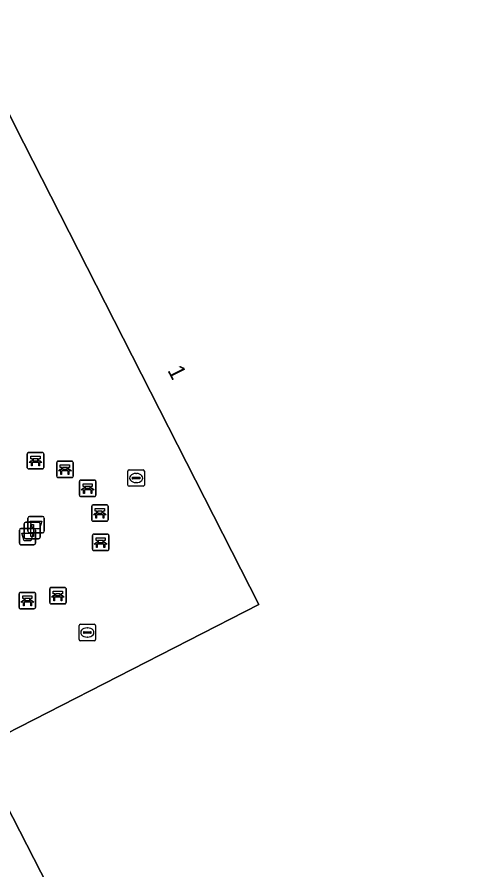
# Model space of a CAD drawing. Extents: x 158455 to 159797, y 387218 to 388672.
# Drawn here: x 159149.7 to 159177.5, y 387581.8 to 387633.9 of the extents above; entities that cross this region are included whole.
import ezdxf

# ---------------------------------------------------------------- set-up
doc = ezdxf.new("R2010")
doc.units = 0
for name, color, linetype in [('IMGEO_Afvalbak', 7, 'Continuous'), ('IMGEO_Bank', 7, 'Continuous'), ('IMGEO_Kolk', 7, 'Continuous'), ('IMGEO_Lichtmast', 7, 'Continuous'), ('IMGEO_Pand', 7, 'Continuous'), ('IMGEO_Pand_nummerreeks', 7, 'Continuous'), ('IMGEO_Voetpad_open', 7, 'Continuous')]:
    doc.layers.add(name, color=color, linetype=linetype)

msp = doc.modelspace()

# ---------------------------------------------------------------- linework, layer by layer
at = {"layer": 'IMGEO_Afvalbak'}
for p, q in [((159150.321, 387602.529), (159150.321, 387603.329)), ((159150.321, 387603.329), (159150.321, 387602.529)), ((159150.421, 387603.429), (159151.211, 387603.429)), ((159151.211, 387603.429), (159150.421, 387603.429)), ((159151.311, 387603.329), (159151.311, 387602.529)), ((159151.311, 387602.529), (159151.311, 387603.329)), ((159149.895, 387602.703), (159150.685, 387602.703)), ((159150.685, 387602.703), (159149.895, 387602.703)), ((159149.795, 387601.803), (159149.795, 387602.603)), ((159149.795, 387602.603), (159149.795, 387601.803)), ((159151.211, 387602.429), (159150.421, 387602.429)), ((159150.421, 387602.429), (159151.211, 387602.429)), ((159150.785, 387602.603), (159150.785, 387601.803)), ((159150.785, 387601.803), (159150.785, 387602.603)), ((159150.685, 387601.703), (159149.895, 387601.703)), ((159149.895, 387601.703), (159150.685, 387601.703))]:
    msp.add_line(p, q, dxfattribs=at)
for points in [[(159150.464, 387603.143), (159151.168, 387603.143), (159151.019, 387602.673), (159150.613, 387602.673), (159150.464, 387603.143)], [(159149.938, 387602.417), (159150.642, 387602.417), (159150.493, 387601.947), (159150.087, 387601.947), (159149.938, 387602.417)]]:
    msp.add_lwpolyline(points, dxfattribs=at)
for centre, start, end in [((159150.421, 387603.329), 90, 180), ((159150.421, 387603.329), 90, 180), ((159151.211, 387603.329), 0, 90), ((159151.211, 387603.329), 360, 90), ((159149.895, 387602.603), 90, 180), ((159149.895, 387602.603), 90, 180), ((159150.685, 387602.603), 0, 90), ((159150.685, 387602.603), 360, 90), ((159150.421, 387602.529), 180, 270), ((159150.421, 387602.529), 180, 270), ((159151.211, 387602.529), 270, 0), ((159151.211, 387602.529), 270, 0), ((159149.895, 387601.803), 180, 270), ((159149.895, 387601.803), 180, 270), ((159150.685, 387601.803), 270, 0), ((159150.685, 387601.803), 270, 0)]:
    msp.add_arc(centre, 0.1, start, end, dxfattribs=at)
at = {"layer": 'IMGEO_Bank'}
for p, q in [((159150.281, 387606.412), (159150.281, 387607.253)), ((159150.281, 387607.253), (159150.281, 387606.412)), ((159150.356, 387607.337), (159151.197, 387607.337)), ((159151.197, 387607.337), (159150.356, 387607.337)), ((159150.59, 387606.843), (159150.59, 387606.949)), ((159150.634, 387606.949), (159150.634, 387606.843)), ((159150.922, 387606.955), (159150.64, 387606.955)), ((159150.928, 387606.843), (159150.928, 387606.949)), ((159150.972, 387606.949), (159150.972, 387606.843)), ((159151.281, 387607.262), (159151.281, 387606.421)), ((159151.281, 387606.421), (159151.281, 387607.262)), ((159150.978, 387606.735), (159150.585, 387606.735)), ((159150.64, 387606.837), (159150.922, 387606.837)), ((159152.077, 387605.886), (159152.077, 387606.727)), ((159152.077, 387606.727), (159152.077, 387605.886)), ((159152.152, 387606.811), (159152.993, 387606.811)), ((159152.993, 387606.811), (159152.152, 387606.811)), ((159152.386, 387606.317), (159152.386, 387606.423)), ((159152.43, 387606.423), (159152.43, 387606.317)), ((159152.718, 387606.429), (159152.436, 387606.429)), ((159152.724, 387606.317), (159152.724, 387606.423)), ((159152.768, 387606.423), (159152.768, 387606.317)), ((159153.077, 387606.736), (159153.077, 387605.895)), ((159153.077, 387605.895), (159153.077, 387606.736)), ((159151.206, 387606.337), (159150.365, 387606.337)), ((159150.365, 387606.337), (159151.206, 387606.337)), ((159152.774, 387606.209), (159152.381, 387606.209)), ((159152.436, 387606.311), (159152.718, 387606.311)), ((159153.002, 387605.811), (159152.161, 387605.811)), ((159152.161, 387605.811), (159153.002, 387605.811)), ((159153.467, 387604.726), (159153.467, 387605.567)), ((159153.467, 387605.567), (159153.467, 387604.726)), ((159153.542, 387605.651), (159154.383, 387605.651)), ((159154.383, 387605.651), (159153.542, 387605.651)), ((159154.467, 387605.576), (159154.467, 387604.735)), ((159154.467, 387604.735), (159154.467, 387605.576)), ((159154.164, 387605.049), (159153.771, 387605.049)), ((159153.776, 387605.157), (159153.776, 387605.263)), ((159153.82, 387605.263), (159153.82, 387605.157)), ((159154.108, 387605.269), (159153.826, 387605.269)), ((159153.826, 387605.151), (159154.108, 387605.151)), ((159154.114, 387605.157), (159154.114, 387605.263)), ((159154.158, 387605.263), (159154.158, 387605.157)), ((159154.392, 387604.651), (159153.551, 387604.651)), ((159153.551, 387604.651), (159154.392, 387604.651)), ((159154.21, 387603.213), (159154.21, 387604.054)), ((159154.21, 387604.054), (159154.21, 387603.213)), ((159154.285, 387604.138), (159155.126, 387604.138)), ((159155.126, 387604.138), (159154.285, 387604.138)), ((159154.519, 387603.644), (159154.519, 387603.75)), ((159154.563, 387603.75), (159154.563, 387603.644)), ((159154.851, 387603.756), (159154.569, 387603.756)), ((159154.857, 387603.644), (159154.857, 387603.75)), ((159154.901, 387603.75), (159154.901, 387603.644)), ((159155.21, 387604.063), (159155.21, 387603.222)), ((159155.21, 387603.222), (159155.21, 387604.063)), ((159154.907, 387603.536), (159154.514, 387603.536)), ((159154.569, 387603.638), (159154.851, 387603.638)), ((159155.135, 387603.138), (159154.294, 387603.138)), ((159154.294, 387603.138), (159155.135, 387603.138)), ((159154.257, 387601.426), (159154.257, 387602.267)), ((159154.257, 387602.267), (159154.257, 387601.426)), ((159154.332, 387602.351), (159155.173, 387602.351)), ((159155.173, 387602.351), (159154.332, 387602.351)), ((159155.257, 387602.276), (159155.257, 387601.435)), ((159155.257, 387601.435), (159155.257, 387602.276)), ((159154.954, 387601.749), (159154.561, 387601.749)), ((159154.566, 387601.857), (159154.566, 387601.963)), ((159154.61, 387601.963), (159154.61, 387601.857)), ((159154.898, 387601.969), (159154.616, 387601.969)), ((159154.616, 387601.851), (159154.898, 387601.851)), ((159154.904, 387601.857), (159154.904, 387601.963)), ((159154.948, 387601.963), (159154.948, 387601.857)), ((159155.182, 387601.351), (159154.341, 387601.351)), ((159154.341, 387601.351), (159155.182, 387601.351)), ((159151.722, 387599.099), (159152.563, 387599.099)), ((159152.563, 387599.099), (159151.722, 387599.099)), ((159149.785, 387597.872), (159149.785, 387598.713)), ((159149.785, 387598.713), (159149.785, 387597.872)), ((159149.86, 387598.797), (159150.701, 387598.797)), ((159150.701, 387598.797), (159149.86, 387598.797)), ((159150.785, 387598.722), (159150.785, 387597.881)), ((159150.785, 387597.881), (159150.785, 387598.722)), ((159151.647, 387598.174), (159151.647, 387599.015)), ((159151.647, 387599.015), (159151.647, 387598.174)), ((159151.956, 387598.605), (159151.956, 387598.711)), ((159152, 387598.711), (159152, 387598.605)), ((159152.288, 387598.717), (159152.006, 387598.717)), ((159152.006, 387598.599), (159152.288, 387598.599)), ((159152.294, 387598.605), (159152.294, 387598.711)), ((159152.338, 387598.711), (159152.338, 387598.605)), ((159152.647, 387599.024), (159152.647, 387598.183)), ((159152.647, 387598.183), (159152.647, 387599.024)), ((159150.482, 387598.195), (159150.089, 387598.195)), ((159150.094, 387598.303), (159150.094, 387598.409)), ((159150.138, 387598.409), (159150.138, 387598.303)), ((159150.426, 387598.415), (159150.144, 387598.415)), ((159150.144, 387598.297), (159150.426, 387598.297)), ((159150.432, 387598.303), (159150.432, 387598.409)), ((159150.476, 387598.409), (159150.476, 387598.303)), ((159152.572, 387598.099), (159151.731, 387598.099)), ((159151.731, 387598.099), (159152.572, 387598.099)), ((159152.344, 387598.497), (159151.951, 387598.497)), ((159150.71, 387597.797), (159149.869, 387597.797)), ((159149.869, 387597.797), (159150.71, 387597.797))]:
    msp.add_line(p, q, dxfattribs=at)
for points in [[(159150.584, 387606.955), (159150.498, 387606.955), (159150.498, 387607.116), (159151.061, 387607.116), (159151.061, 387606.955), (159150.978, 387606.955)], [(159150.528, 387606.735), (159150.386, 387606.735), (159150.498, 387606.837), (159150.584, 387606.837)], [(159150.578, 387606.728), (159150.578, 387606.521), (159150.535, 387606.521), (159150.535, 387606.728)], [(159150.978, 387606.837), (159151.061, 387606.837), (159151.173, 387606.735), (159151.034, 387606.735)], [(159151.028, 387606.728), (159151.028, 387606.521), (159150.984, 387606.521), (159150.984, 387606.728)], [(159152.38, 387606.429), (159152.294, 387606.429), (159152.294, 387606.59), (159152.857, 387606.59), (159152.857, 387606.429), (159152.774, 387606.429)], [(159152.324, 387606.209), (159152.182, 387606.209), (159152.294, 387606.311), (159152.38, 387606.311)], [(159152.374, 387606.202), (159152.374, 387605.995), (159152.331, 387605.995), (159152.331, 387606.202)], [(159152.774, 387606.311), (159152.857, 387606.311), (159152.969, 387606.209), (159152.83, 387606.209)], [(159152.824, 387606.202), (159152.824, 387605.995), (159152.78, 387605.995), (159152.78, 387606.202)], [(159153.77, 387605.269), (159153.684, 387605.269), (159153.684, 387605.43), (159154.247, 387605.43), (159154.247, 387605.269), (159154.164, 387605.269)], [(159153.714, 387605.049), (159153.572, 387605.049), (159153.684, 387605.151), (159153.77, 387605.151)], [(159153.764, 387605.042), (159153.764, 387604.835), (159153.721, 387604.835), (159153.721, 387605.042)], [(159154.164, 387605.151), (159154.247, 387605.151), (159154.359, 387605.049), (159154.22, 387605.049)], [(159154.214, 387605.042), (159154.214, 387604.835), (159154.17, 387604.835), (159154.17, 387605.042)], [(159154.513, 387603.756), (159154.427, 387603.756), (159154.427, 387603.917), (159154.99, 387603.917), (159154.99, 387603.756), (159154.907, 387603.756)], [(159154.457, 387603.536), (159154.315, 387603.536), (159154.427, 387603.638), (159154.513, 387603.638)], [(159154.507, 387603.529), (159154.507, 387603.322), (159154.464, 387603.322), (159154.464, 387603.529)], [(159154.907, 387603.638), (159154.99, 387603.638), (159155.102, 387603.536), (159154.963, 387603.536)], [(159154.957, 387603.529), (159154.957, 387603.322), (159154.913, 387603.322), (159154.913, 387603.529)], [(159154.504, 387601.749), (159154.362, 387601.749), (159154.474, 387601.851), (159154.56, 387601.851)], [(159154.56, 387601.969), (159154.474, 387601.969), (159154.474, 387602.13), (159155.037, 387602.13), (159155.037, 387601.969), (159154.954, 387601.969)], [(159154.554, 387601.742), (159154.554, 387601.535), (159154.511, 387601.535), (159154.511, 387601.742)], [(159154.954, 387601.851), (159155.037, 387601.851), (159155.149, 387601.749), (159155.01, 387601.749)], [(159155.004, 387601.742), (159155.004, 387601.535), (159154.96, 387601.535), (159154.96, 387601.742)], [(159150.088, 387598.415), (159150.002, 387598.415), (159150.002, 387598.576), (159150.565, 387598.576), (159150.565, 387598.415), (159150.482, 387598.415)], [(159151.894, 387598.497), (159151.752, 387598.497), (159151.864, 387598.599), (159151.95, 387598.599)], [(159151.95, 387598.717), (159151.864, 387598.717), (159151.864, 387598.878), (159152.427, 387598.878), (159152.427, 387598.717), (159152.344, 387598.717)], [(159152.344, 387598.599), (159152.427, 387598.599), (159152.539, 387598.497), (159152.4, 387598.497)], [(159150.032, 387598.195), (159149.89, 387598.195), (159150.002, 387598.297), (159150.088, 387598.297)], [(159150.082, 387598.188), (159150.082, 387597.981), (159150.039, 387597.981), (159150.039, 387598.188)], [(159150.482, 387598.297), (159150.565, 387598.297), (159150.677, 387598.195), (159150.538, 387598.195)], [(159150.532, 387598.188), (159150.532, 387597.981), (159150.488, 387597.981), (159150.488, 387598.188)], [(159151.944, 387598.49), (159151.944, 387598.283), (159151.901, 387598.283), (159151.901, 387598.49)], [(159152.394, 387598.49), (159152.394, 387598.283), (159152.35, 387598.283), (159152.35, 387598.49)]]:
    msp.add_lwpolyline(points, dxfattribs=at)
for centre, radius, start, end in [((159150.359, 387607.259), 0.0779, 92.4484, 184.2845), ((159150.359, 387607.259), 0.0779, 92.4484, 184.2845), ((159150.583, 387606.948), 0.00671, 2.8957, 87.1043), ((159150.64, 387606.948), 0.00671, 92.8957, 177.1043), ((159150.922, 387606.948), 0.00671, 2.8957, 87.1043), ((159150.979, 387606.948), 0.00671, 92.8957, 177.1043), ((159151.203, 387607.259), 0.0779, 2.4484, 94.2845), ((159151.203, 387607.259), 0.0779, 2.4484, 94.2845), ((159150.359, 387606.415), 0.0779, 182.4484, 274.2845), ((159150.359, 387606.415), 0.0779, 182.4484, 274.2845), ((159150.528, 387606.728), 0.00671, 2.8957, 87.1043), ((159150.585, 387606.728), 0.00671, 92.8957, 177.1043), ((159150.583, 387606.844), 0.00671, 272.8957, 357.1043), ((159150.64, 387606.844), 0.00671, 182.8957, 267.1043), ((159150.922, 387606.844), 0.00671, 272.8957, 357.1043), ((159150.979, 387606.844), 0.00671, 182.8957, 267.1043), ((159150.977, 387606.728), 0.00671, 2.8957, 87.1043), ((159151.034, 387606.728), 0.00671, 92.8957, 177.1043), ((159151.203, 387606.415), 0.0779, 272.4484, 4.2845), ((159151.203, 387606.415), 0.0779, 272.4484, 4.2845), ((159152.155, 387606.733), 0.0779, 92.4484, 184.2845), ((159152.155, 387606.733), 0.0779, 92.4484, 184.2845), ((159152.379, 387606.422), 0.00671, 2.8957, 87.1043), ((159152.436, 387606.422), 0.00671, 92.8957, 177.1043), ((159152.718, 387606.422), 0.00671, 2.8957, 87.1043), ((159152.775, 387606.422), 0.00671, 92.8957, 177.1043), ((159152.999, 387606.733), 0.0779, 2.4484, 94.2845), ((159152.999, 387606.733), 0.0779, 2.4484, 94.2845), ((159152.155, 387605.889), 0.0779, 182.4484, 274.2845), ((159152.155, 387605.889), 0.0779, 182.4484, 274.2845), ((159152.324, 387606.202), 0.00671, 2.8957, 87.1043), ((159152.381, 387606.202), 0.00671, 92.8957, 177.1043), ((159152.379, 387606.318), 0.00671, 272.8957, 357.1043), ((159152.436, 387606.318), 0.00671, 182.8957, 267.1043), ((159152.718, 387606.318), 0.00671, 272.8957, 357.1043), ((159152.775, 387606.318), 0.00671, 182.8957, 267.1043), ((159152.773, 387606.202), 0.00671, 2.8957, 87.1043), ((159152.83, 387606.202), 0.00671, 92.8957, 177.1043), ((159152.999, 387605.889), 0.0779, 272.4484, 4.2845), ((159152.999, 387605.889), 0.0779, 272.4484, 4.2845), ((159153.545, 387605.573), 0.0779, 92.4484, 184.2845), ((159153.545, 387605.573), 0.0779, 92.4484, 184.2845), ((159154.389, 387605.573), 0.0779, 2.4484, 94.2845), ((159154.389, 387605.573), 0.0779, 2.4484, 94.2845), ((159153.714, 387605.042), 0.00671, 2.8957, 87.1043), ((159153.771, 387605.042), 0.00671, 92.8957, 177.1043), ((159153.769, 387605.262), 0.00671, 2.8957, 87.1043), ((159153.769, 387605.158), 0.00671, 272.8957, 357.1043), ((159153.826, 387605.262), 0.00671, 92.8957, 177.1043), ((159153.826, 387605.158), 0.00671, 182.8957, 267.1043), ((159154.108, 387605.262), 0.00671, 2.8957, 87.1043), ((159154.108, 387605.158), 0.00671, 272.8957, 357.1043), ((159154.165, 387605.262), 0.00671, 92.8957, 177.1043), ((159154.165, 387605.158), 0.00671, 182.8957, 267.1043), ((159154.163, 387605.042), 0.00671, 2.8957, 87.1043), ((159154.22, 387605.042), 0.00671, 92.8957, 177.1043), ((159153.545, 387604.729), 0.0779, 182.4484, 274.2845), ((159153.545, 387604.729), 0.0779, 182.4484, 274.2845), ((159154.389, 387604.729), 0.0779, 272.4484, 4.2845), ((159154.389, 387604.729), 0.0779, 272.4484, 4.2845), ((159154.288, 387604.06), 0.0779, 92.4484, 184.2845), ((159154.288, 387604.06), 0.0779, 92.4484, 184.2845), ((159154.512, 387603.749), 0.00671, 2.8957, 87.1043), ((159154.569, 387603.749), 0.00671, 92.8957, 177.1043), ((159154.851, 387603.749), 0.00671, 2.8957, 87.1043), ((159154.908, 387603.749), 0.00671, 92.8957, 177.1043), ((159155.132, 387604.06), 0.0779, 2.4484, 94.2845), ((159155.132, 387604.06), 0.0779, 2.4484, 94.2845), ((159154.457, 387603.529), 0.00671, 2.8957, 87.1043), ((159154.514, 387603.529), 0.00671, 92.8957, 177.1043), ((159154.512, 387603.645), 0.00671, 272.8957, 357.1043), ((159154.569, 387603.645), 0.00671, 182.8957, 267.1043), ((159154.851, 387603.645), 0.00671, 272.8957, 357.1043), ((159154.908, 387603.645), 0.00671, 182.8957, 267.1043), ((159154.906, 387603.529), 0.00671, 2.8957, 87.1043), ((159154.963, 387603.529), 0.00671, 92.8957, 177.1043), ((159155.132, 387603.216), 0.0779, 272.4484, 4.2845), ((159155.132, 387603.216), 0.0779, 272.4484, 4.2845), ((159154.288, 387603.216), 0.0779, 182.4484, 274.2845), ((159154.288, 387603.216), 0.0779, 182.4484, 274.2845), ((159154.335, 387602.273), 0.0779, 92.4484, 184.2845), ((159154.335, 387602.273), 0.0779, 92.4484, 184.2845), ((159155.179, 387602.273), 0.0779, 2.4484, 94.2845), ((159155.179, 387602.273), 0.0779, 2.4484, 94.2845), ((159154.504, 387601.742), 0.00671, 2.8957, 87.1043), ((159154.561, 387601.742), 0.00671, 92.8957, 177.1043), ((159154.559, 387601.962), 0.00671, 2.8957, 87.1043), ((159154.559, 387601.858), 0.00671, 272.8957, 357.1043), ((159154.616, 387601.962), 0.00671, 92.8957, 177.1043), ((159154.616, 387601.858), 0.00671, 182.8957, 267.1043), ((159154.898, 387601.962), 0.00671, 2.8957, 87.1043), ((159154.898, 387601.858), 0.00671, 272.8957, 357.1043), ((159154.955, 387601.962), 0.00671, 92.8957, 177.1043), ((159154.955, 387601.858), 0.00671, 182.8957, 267.1043), ((159154.953, 387601.742), 0.00671, 2.8957, 87.1043), ((159155.01, 387601.742), 0.00671, 92.8957, 177.1043), ((159154.335, 387601.429), 0.0779, 182.4484, 274.2845), ((159154.335, 387601.429), 0.0779, 182.4484, 274.2845), ((159155.179, 387601.429), 0.0779, 272.4484, 4.2845), ((159155.179, 387601.429), 0.0779, 272.4484, 4.2845), ((159151.725, 387599.021), 0.0779, 92.4484, 184.2845), ((159151.725, 387599.021), 0.0779, 92.4484, 184.2845), ((159152.569, 387599.021), 0.0779, 2.4484, 94.2845), ((159152.569, 387599.021), 0.0779, 2.4484, 94.2845), ((159149.863, 387598.719), 0.0779, 92.4484, 184.2845), ((159149.863, 387598.719), 0.0779, 92.4484, 184.2845), ((159150.707, 387598.719), 0.0779, 2.4484, 94.2845), ((159150.707, 387598.719), 0.0779, 2.4484, 94.2845), ((159151.949, 387598.71), 0.00671, 2.8957, 87.1043), ((159151.949, 387598.606), 0.00671, 272.8957, 357.1043), ((159152.006, 387598.71), 0.00671, 92.8957, 177.1043), ((159152.006, 387598.606), 0.00671, 182.8957, 267.1043), ((159152.288, 387598.71), 0.00671, 2.8957, 87.1043), ((159152.288, 387598.606), 0.00671, 272.8957, 357.1043), ((159152.345, 387598.71), 0.00671, 92.8957, 177.1043), ((159152.345, 387598.606), 0.00671, 182.8957, 267.1043), ((159150.032, 387598.188), 0.00671, 2.8957, 87.1043), ((159150.089, 387598.188), 0.00671, 92.8957, 177.1043), ((159150.087, 387598.408), 0.00671, 2.8957, 87.1043), ((159150.087, 387598.304), 0.00671, 272.8957, 357.1043), ((159150.144, 387598.408), 0.00671, 92.8957, 177.1043), ((159150.144, 387598.304), 0.00671, 182.8957, 267.1043), ((159150.426, 387598.408), 0.00671, 2.8957, 87.1043), ((159150.426, 387598.304), 0.00671, 272.8957, 357.1043), ((159150.483, 387598.408), 0.00671, 92.8957, 177.1043), ((159150.483, 387598.304), 0.00671, 182.8957, 267.1043), ((159150.481, 387598.188), 0.00671, 2.8957, 87.1043), ((159150.538, 387598.188), 0.00671, 92.8957, 177.1043), ((159151.725, 387598.177), 0.0779, 182.4484, 274.2845), ((159151.725, 387598.177), 0.0779, 182.4484, 274.2845), ((159151.894, 387598.49), 0.00671, 2.8957, 87.1043), ((159151.951, 387598.49), 0.00671, 92.8957, 177.1043), ((159152.343, 387598.49), 0.00671, 2.8957, 87.1043), ((159152.4, 387598.49), 0.00671, 92.8957, 177.1043), ((159152.569, 387598.177), 0.0779, 272.4484, 4.2845), ((159152.569, 387598.177), 0.0779, 272.4484, 4.2845), ((159149.863, 387597.875), 0.0779, 182.4484, 274.2845), ((159149.863, 387597.875), 0.0779, 182.4484, 274.2845), ((159150.707, 387597.875), 0.0779, 272.4484, 4.2845), ((159150.707, 387597.875), 0.0779, 272.4484, 4.2845)]:
    msp.add_arc(centre, radius, start, end, dxfattribs=at)
at = {"layer": 'IMGEO_Kolk'}
for p, q in [((159156.423, 387605.353), (159156.423, 387606.205)), ((159156.498, 387606.279), (159157.35, 387606.279)), ((159156.725, 387605.822), (159157.123, 387605.822)), ((159156.911, 387606.059), (159156.936, 387606.059)), ((159157.424, 387606.205), (159157.424, 387605.353)), ((159156.682, 387605.773), (159156.682, 387605.785)), ((159157.12, 387605.736), (159156.722, 387605.736)), ((159156.934, 387605.499), (159156.909, 387605.499)), ((159157.166, 387605.785), (159157.166, 387605.773)), ((159157.35, 387605.279), (159156.498, 387605.279)), ((159153.443, 387595.919), (159153.443, 387596.771)), ((159153.518, 387596.845), (159154.37, 387596.845)), ((159153.931, 387596.625), (159153.956, 387596.625)), ((159154.444, 387596.771), (159154.444, 387595.919)), ((159153.702, 387596.339), (159153.702, 387596.351)), ((159154.14, 387596.302), (159153.742, 387596.302)), ((159153.745, 387596.388), (159154.143, 387596.388)), ((159153.954, 387596.065), (159153.929, 387596.065)), ((159154.186, 387596.351), (159154.186, 387596.339)), ((159154.37, 387595.845), (159153.518, 387595.845))]:
    msp.add_line(p, q, dxfattribs=at)
for points in [[(159156.423, 387605.353), (159156.423, 387606.205)], [(159156.498, 387606.279), (159157.35, 387606.279)], [(159157.424, 387606.205), (159157.424, 387605.353)], [(159157.35, 387605.279), (159156.498, 387605.279)], [(159153.443, 387595.919), (159153.443, 387596.771)], [(159153.518, 387596.845), (159154.37, 387596.845)], [(159154.444, 387596.771), (159154.444, 387595.919)], [(159154.37, 387595.845), (159153.518, 387595.845)]]:
    msp.add_lwpolyline(points, dxfattribs=at)
for centre, radius, start, end in [((159156.5, 387606.203), 0.0765, 91.552, 178.448), ((159156.5, 387606.203), 0.0765, 91.552, 178.448), ((159156.722, 387605.782), 0.0403, 85.8775, 175.7526), ((159157.127, 387605.784), 0.0386, 1.7309, 96.639), ((159157.348, 387606.203), 0.0765, 1.552, 88.448), ((159157.348, 387606.203), 0.0765, 1.552, 88.448), ((159156.5, 387605.355), 0.0765, 181.552, 268.448), ((159156.5, 387605.355), 0.0765, 181.552, 268.448), ((159156.719, 387605.772), 0.0366, 178.938, 274.7102), ((159157.123, 387605.779), 0.043, 264.8664, 352.4533), ((159157.348, 387605.355), 0.0765, 271.552, 358.448), ((159157.348, 387605.355), 0.0765, 271.552, 358.448), ((159153.52, 387596.769), 0.0765, 91.552, 178.448), ((159153.52, 387596.769), 0.0765, 91.552, 178.448), ((159154.368, 387596.769), 0.0765, 1.552, 88.448), ((159154.368, 387596.769), 0.0765, 1.552, 88.448), ((159153.742, 387596.348), 0.0403, 85.8775, 175.7526), ((159153.739, 387596.338), 0.0366, 178.938, 274.7102), ((159154.143, 387596.345), 0.043, 264.8664, 352.4533), ((159154.147, 387596.35), 0.0386, 1.7309, 96.639), ((159153.52, 387595.921), 0.0765, 181.552, 268.448), ((159153.52, 387595.921), 0.0765, 181.552, 268.448), ((159154.368, 387595.921), 0.0765, 271.552, 358.448), ((159154.368, 387595.921), 0.0765, 271.552, 358.448)]:
    msp.add_arc(centre, radius, start, end, dxfattribs=at)
for centre, major_axis, ratio, start_param, end_param in [((159156.91, 387605.779), (-0.387, 0.002), 0.722429, 4.712389, 7.853982), ((159156.935, 387605.779), (-0.39, 0.002), 0.717154, 1.570796, 4.712389), ((159153.93, 387596.345), (-0.387, 0.002), 0.722429, 4.712389, 7.853982), ((159153.955, 387596.345), (-0.39, 0.002), 0.717154, 1.570796, 4.712389)]:
    msp.add_ellipse(centre, major_axis=major_axis, ratio=ratio, start_param=start_param, end_param=end_param, dxfattribs=at)
at = {"layer": 'IMGEO_Lichtmast'}
for p, q in [((159150.083, 387602.176), (159150.083, 387602.976)), ((159150.083, 387602.976), (159150.083, 387602.176)), ((159150.183, 387603.076), (159150.973, 387603.076)), ((159150.973, 387603.076), (159150.183, 387603.076)), ((159151.073, 387602.976), (159151.073, 387602.176)), ((159151.073, 387602.176), (159151.073, 387602.976)), ((159150.973, 387602.076), (159150.183, 387602.076)), ((159150.183, 387602.076), (159150.973, 387602.076))]:
    msp.add_line(p, q, dxfattribs=at)
msp.add_lwpolyline([(159150.503, 387602.951), (159150.653, 387602.951), (159150.653, 387602.201), (159150.503, 387602.201), (159150.503, 387602.951)], dxfattribs=at)
for centre, start, end in [((159150.183, 387602.976), 90, 180), ((159150.183, 387602.976), 90, 180), ((159150.973, 387602.976), 0, 90), ((159150.973, 387602.976), 360, 90), ((159150.183, 387602.176), 180, 270), ((159150.183, 387602.176), 180, 270), ((159150.973, 387602.176), 270, 0), ((159150.973, 387602.176), 270, 0)]:
    msp.add_arc(centre, 0.1, start, end, dxfattribs=at)
at = {"layer": 'IMGEO_Pand'}
msp.add_lwpolyline([(159243.347, 387534.407), (159215.411, 387588.729), (159212.188, 387595.01), (159189.1, 387640.009), (159187.255, 387643.604), (159182.773, 387652.336), (159182.568, 387652.736), (159174.864, 387648.787), (159175.591, 387647.372), (159153.723, 387636.146), (159152.628, 387635.584), (159151.892, 387637.005), (159146.311, 387634.134), (159146.16, 387634.056), (159146.325, 387633.726), (159149.527, 387627.308), (159164.416, 387598.056), (159147.23, 387589.258), (159159.255, 387565.769), (159165.254, 387557.853), (159172.669, 387543.33)], dxfattribs=at)
at = {"layer": 'IMGEO_Voetpad_open'}
msp.add_lwpolyline([(159149.527, 387627.308), (159146.325, 387633.726), (159142.127, 387631.588), (159142.115, 387631.582), (159142.476, 387630.877), (159127.461, 387623.17), (159145.335, 387588.289), (159147.23, 387589.258), (159164.416, 387598.056)], close=True, dxfattribs=at)
msp.add_lwpolyline([(159172.669, 387543.33), (159165.254, 387557.853), (159159.255, 387565.769), (159147.23, 387589.258), (159145.335, 387588.289), (159164.36, 387551.228), (159157.942, 387549.52), (159155.38, 387548.834), (159139.324, 387544.489)], dxfattribs=at)

# ---------------------------------------------------------------- texts
at = {"layer": 'IMGEO_Pand_nummerreeks'}
msp.add_text('1', height=1, rotation=296.7798, dxfattribs=at).set_placement((159158.819, 387612.361))

doc.saveas('drawing.dxf')
